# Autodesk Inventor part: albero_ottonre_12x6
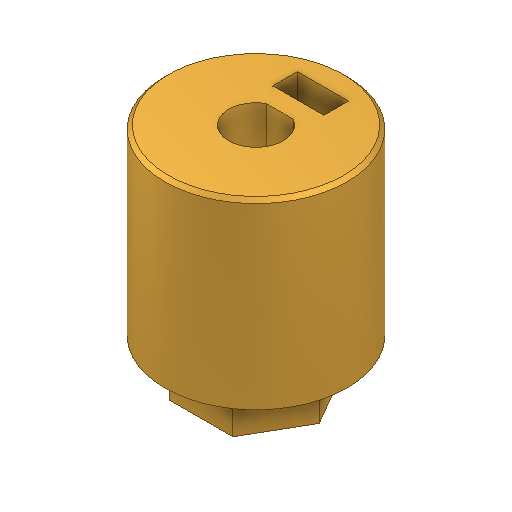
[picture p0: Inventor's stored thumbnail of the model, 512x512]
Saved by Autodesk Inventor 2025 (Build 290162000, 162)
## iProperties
Created: 2025-05
Part Number: albero_ottonre_12x6
Material: Ottone, Giallo chiaro
Document SubType Name: Modeling
Designer: R5800u
Density: 8.47 g/cm^3
Appearance: Ottone - Satinato
Author: R5800u
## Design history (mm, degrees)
node "Annotazioni"
  node "Quota lineare 1" dims "d0" = 12, "d20" = 90 deg, "d48" = 2.8 (derived)
sketch "Schizzo1"
  geometry: L1 (-6.928, 0)-(-3.464, 6); L2 (-3.464, 6)-(3.464, 6); L3 (3.464, 6)-(6.928, 0); L4 (6.928, 0)-(3.464, -6); L5 (3.464, -6)-(-3.464, -6); L6 (-3.464, -6)-(-6.928, 0); 2 further points
  constraints: 12 end point, 1 coincident, 13 other
  dimensions: "d0" = 12 distance between parallel lines of L5 L2
extrude "Estrusione1" new body sketch "Schizzo1" distance "d1" = 4.9; taper "d2" = 0 deg
sketch "Schizzo2"
  geometry: C1 r 10 at (0, 0); 1 further point
  constraints: 1 centre point, 1 coincident
  dimensions: "d3" = 20 diameter of C1
extrude "Estrusione2" join sketch "Schizzo2" distance "d4" = 20; taper "d5" = 0 deg
sketch "Schizzo3"
  geometry: C1 r 10 at (0, 0) reference; 2 further points
  constraints: 1 coincident
hole "Foro1" sketch "Schizzo3" at (0, 0) diameter "d6" = 6; stored, may be unused: countersink angle "d10" = 90 deg, drill point angle "d12" = 0 deg; dims "d7" = 6, "d8" = 12.6, "d9" = 2, "d11" = 12
chamfer "Smusso1" distance "d13" = 0.4; stored, may be unused: second distance "d14" = 2, angle "d15" = 45 deg
sketch "Schizzo4"
  geometry: C1 r 5.5 at (0, 0) reference; 2 further points
  constraints: 1 coincident
hole "Foro2" sketch "Schizzo4" at (0, 0) diameter "d16" = 3.2; stored, may be unused: countersink angle "d20" = 90 deg, drill point angle "d22" = 0 deg; dims "d17" = 6, "d18" = 12.6, "d19" = 2, "d21" = 8.8
sketch "Schizzo5"
  geometry: L1 (-3, 24.9)-(3, 24.9) reference; 2 further points
  dimensions: "d24" = 6 distance from line of L1 point (0, 18.9)
hole "Foro3" sketch "Schizzo5" at (0, 18.9) diameter "d25" = 3.4; stored, may be unused: countersink angle "d29" = 90 deg, drill point angle "d31" = 118 deg; dims "d26" = 6, "d27" = 4, "d28" = 2, "d30" = 8.8
sketch "Schizzo6"
  geometry: C1 r 10 at (0, 0); 1 further point
  constraints: 1 centre point, 1 coincident
  dimensions: "d32" = 20 diameter of C1
extrude "Estrusione3" join sketch "Schizzo6" distance "d33" = 5; taper "d34" = 0 deg
sketch "Schizzo7"
  geometry: L1 (-2.8, 7.35)-(2.8, 7.35); L2 (2.8, 7.35)-(2.8, 4.65); L3 (2.8, 4.65)-(-2.8, 4.65); L4 (-2.8, 4.65)-(-2.8, 7.35); L5 (-2.8, 7.35)-(2.8, 4.65); L6 (2.8, 7.35)-(-2.8, 4.65); 2 further points
  constraints: 12 end point, 2 midpoint, 2 parallel, 1 horizontal, 1 perpendicular
  dimensions: "d35" = 5.6 distance of L2.end L3.end; "d36" = 2.7 distance of L1.end L2.end; "d39" = 6 distance of point (0, 0) point (0, 6)
extrude "Estrusione4" cut sketch "Schizzo7" distance "d37" = 12; taper "d38" = 0 deg
sketch "Schizzo8"
  geometry: L1 (6.928, 4.9)-(0, 4.9) reference; L2 (5.064, 4.9)-(1.864, 4.9) reference; L3 (3.464, 4.9)-(3.464, 9.9); L4 (0.664, 7.9)-(6.264, 7.9); L5 (6.264, 7.9)-(6.264, 10.6); L6 (6.264, 10.6)-(0.664, 10.6); L7 (0.664, 10.6)-(0.664, 7.9); L8 (0.664, 7.9)-(6.264, 10.6); L9 (6.264, 7.9)-(0.664, 10.6); 2 further points
  constraints: 14 end point, 3 midpoint, 2 parallel, 1 horizontal, 1 perpendicular, 1 point on line, 1 vertical
  dimensions: "d56" = 5 distance of L3.start L3.end; "d57" = 5.6 distance of L6.end L5.end; "d58" = 2.7 distance of L5.end L4.end; "d59" = 3 distance between parallel lines of L1 L4
extrude "Estrusione5" cut sketch "Schizzo8" distance "d43" = 4.9; taper "d45" = 0 deg; dims "d44" = 8.8, "d46" = 0
sketch "Schizzo9"
  geometry: C1 r 1.6 at (0, 0) reference; 2 further points
  constraints: 1 coincident
hole "Foro4" sketch "Schizzo9" at (0, 0) diameter "d49" = 3.2; stored, may be unused: countersink angle "d53" = 90 deg, drill point angle "d55" = 118 deg; dims "d50" = 6, "d51" = 6.3, "d52" = 2, "d54" = 8
sketch "Schizzo10"
  geometry: L1 (-1.497, 2.6)-(1.497, 2.6); A1 r 3 centre (0, 0) between (-1.497, 2.6) and (1.497, 2.6); 1 further point
  constraints: 2 end point, 2 point on circle, 1 centre point, 1 coincident, 1 horizontal
  dimensions: "d60" = 2.6 distance from line of point (0, 0) L1; "d63" = 6 diameter of A1
extrude "Estrusione6" join sketch "Schizzo10" stored distance "d61" = 4.9; taper "d62" = 0 deg
sketch "Schizzo11"
  geometry: C1 r 1.7 at (2.8, -6) reference; 2 further points
  constraints: 1 coincident
hole "Foro5" sketch "Schizzo11" at (2.8, -6) diameter "d64" = 3.4; stored, may be unused: countersink angle "d68" = 90 deg, drill point angle "d70" = 118 deg; dims "d65" = 6, "d66" = 4, "d67" = 2, "d69" = 6.75
sketch "Schizzo12"
  geometry: C1 r 1.7 at (2.8, -6) reference; 1 further point
extrude "Estrusione7" cut sketch "Schizzo12" distance "d71" = 10; taper "d72" = 0 deg
node "Solido1"
other parameters: "d47" = 3.18414 (derived)
